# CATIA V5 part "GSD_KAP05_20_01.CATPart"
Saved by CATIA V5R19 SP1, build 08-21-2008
Part number: GSD_REFLECT_01
Definition: Übungsbeispiel für die Funktion Reflexionslinie / ReflectLine.
Description: CATIA V5 Flächenmodellierung  Copyright (c) 2009 Maik Hertha IT Consultants
Bounding box of the stored display mesh (mm): x -49.392 to 58.626, y 1.486 to 32.958, z 5.585 to 48.528
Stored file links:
  \GSD_BUCH_UEBUNG\GSD_KAP05_20_01.CATPart
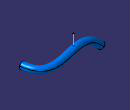
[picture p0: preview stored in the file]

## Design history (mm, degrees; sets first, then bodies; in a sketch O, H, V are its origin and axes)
Parameters
  Sweep_Radius = 5 mm
AxisSystem1 "Absolute Axis System": origin (0, 0, 0), X (1, 0, 0), Y (0, 1, 0), Z (0, 0, 1)
Set1 "Sketches.1"
  Sketch1 on Plane2, origin (0, 0, 0), H (1, 0, 0), V (0, 1, 0)
    spline S1 through (-47.0754, 20.6336) (6.382, 26.3514) (43.6512, 23.1308) (53.8071, 0.0275)
    curve C1
  Plane1: type Equation, A 0, B 1, C 0, Length -20
  Sketch2 on Plane1, origin (0, -20, 0), H (-1, 0, 0), V (0, 0, 1)
    spline S1 through (-53.6493, 22.761) (-25.8056, 25.0457) (8.893, 28.5248) (45.6138, 8.8613)
    curve C1
Set2 "Reflect Support"
  Combine1: Curve1 Sketch2.C1, Curve2 Sketch1.C1
  Sweep1: type Circle, Guide Combine1, Radius 5 {= Sweep_Radius}
Set3 "Helpers.1"
  Plane2: type Equation, A 0, B 0, C 1, Length 0
  Plane3: type Equation, A 1, B 0, C 0, RefAxis AxisSystem1, Length 0
  Intersect1: ToIntersect1 Plane3, ToIntersect2 Combine1
  Line1: type PtDir, Direction (0, 0, 1), Start 5 {= Sweep_Radius}, End 20, RefPoint Intersect1
Set4 "Reflect normal"
  DatumSurface1: linked copy from another document
  Line2: linked copy from another document
Set5 "Reflect along direction"
  DatumSurface2: linked copy from another document
  Line3: linked copy from another document
Set6 "Reflect Conic"
  DatumSurface3: linked copy from another document
  Point1 "Lichtpunkt": (0, 0, 200), in AxisSystem1
Body1 (main body)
